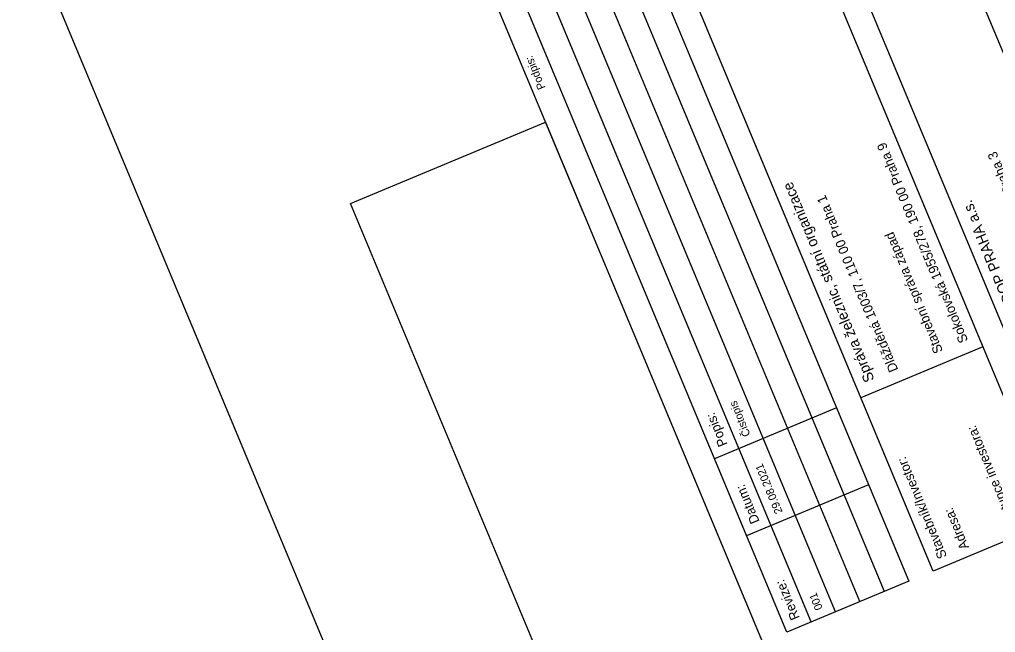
# Model space of a CAD drawing. Extents: x -834064 to -833847, y -1109181 to -1108930.
# Drawn here: x -834064.4 to -833967.4, y -1109058.9 to -1108998 of the extents above; entities that cross this region are included whole.
import ezdxf

# ---------------------------------------------------------------- set-up
doc = ezdxf.new("R2010")
doc.units = 0
for name, color, linetype in [('Rozpiska_pola_3', 7, 'Continuous'), ('Rozpiska_pole_4', 7, 'Continuous'), ('Rozpiska_pole_5', 7, 'Continuous'), ('Rozpiska_pole_6', 7, 'Continuous'), ('Rozpiska_pole_7', 7, 'Continuous'), ('Rozpiska_SŽ_netisknutelná', 7, 'Continuous'), ('Vrstva 63', 7, 'Continuous')]:
    doc.layers.add(name, color=color, linetype=linetype)

msp = doc.modelspace()

# ---------------------------------------------------------------- linework, layer by layer
at = {"layer": 'Rozpiska_pola_3'}
msp.add_line((-834008.401, -1109017.203), (-834024.933, -1108977.534), dxfattribs=at)
at = {"layer": 'Rozpiska_pole_4'}
for p, q in [((-833978.485, -1109054.868), (-834012.818, -1108972.485)), ((-833980.908, -1109055.877), (-834015.241, -1108973.495)), ((-833983.331, -1109056.887), (-834017.664, -1108974.505)), ((-833985.754, -1109057.897), (-834020.087, -1108975.514)), ((-833983.242, -1109036.63), (-833995.357, -1109041.679)), ((-833980.051, -1109044.287), (-833992.166, -1109049.336))]:
    msp.add_line(p, q, dxfattribs=at)
msp.add_lwpolyline([(-833988.177, -1109058.907), (-834022.51, -1108976.524), (-834010.395, -1108971.475), (-833976.062, -1109053.858)], close=True, dxfattribs=at)
at = {"layer": 'Rozpiska_pole_5'}
msp.add_line((-833968.704, -1109030.572), (-833980.819, -1109035.62), dxfattribs=at)
msp.add_lwpolyline([(-833973.639, -1109052.848), (-834007.972, -1108970.466), (-833995.857, -1108965.417), (-833961.524, -1109047.799)], close=True, dxfattribs=at)
at = {"layer": 'Rozpiska_pole_6'}
msp.add_lwpolyline([(-833959.101, -1109046.789), (-833993.434, -1108964.407), (-833969.203, -1108954.309), (-833934.871, -1109036.692)], close=True, dxfattribs=at)
at = {"layer": 'Rozpiska_pole_7'}
msp.add_line((-833949.409, -1109042.75), (-833983.742, -1108960.368), dxfattribs=at)
at = {"layer": 'Rozpiska_SŽ_netisknutelná'}
msp.add_lwpolyline([(-834009.985, -1109067.995), (-834031.523, -1109016.312), (-834012.139, -1109008.234), (-833990.6, -1109059.916)], close=True, dxfattribs=at)
at = {"layer": 'Vrstva 63'}
msp.add_line((-833983.612, -1109181.188), (-834064.392, -1108987.352), dxfattribs=at)

# ---------------------------------------------------------------- texts
at = {"layer": 'Rozpiska_pola_3'}
msp.add_text('Podpis:', height=0.7875, rotation=112.62355, dxfattribs=at).set_placement((-834012.139, -1109004.821))
at = {"layer": 'Rozpiska_pole_4'}
for s, height, p in [('Čistopis', 0.7875, (-833991.77, -1109039.305)), ('Popis:', 0.945, (-833994.047, -1109040.254)), ('29.08.2021', 0.7875, (-833988.579, -1109046.961)), ('Datum:', 0.945, (-833990.857, -1109047.91)), ('Revize:', 0.945, (-833986.868, -1109057.481)), ('001', 0.7875, (-833984.59, -1109056.532))]:
    msp.add_text(s, height=height, rotation=112.62355, dxfattribs=at).set_placement(p)
at = {"layer": 'Rozpiska_pole_5'}
for s, height, p in [('Správa železnic, státní organizace', 1.05, (-833979.447, -1109033.827)), ('Zástupce investora:', 0.945, (-833965.216, -1109048.458)), ('Stavebník/Investor:', 0.945, (-833972.243, -1109051.386)), ('Adresa:', 0.945, (-833970.062, -1109050.478))]:
    msp.add_text(s, height=height, rotation=112.62355, dxfattribs=at).set_placement(p)
at = {"layer": 'Rozpiska_pole_6'}
for s, height, p in [('Sokolovská 1955/278, 190 00 Praha 9', 0.945, (-833970.146, -1109029.952)), ('Olšanská 1a, 130 80 Praha 3', 0.945, (-833961.1, -1109026.182)), ('Dlážděná 1003/7, 110 00 Praha 1', 0.945, (-833977.095, -1109032.847)), ('SUDOP PRAHA a.s.', 1.05, (-833964.909, -1109027.769)), ('Stavební správa západ', 0.945, (-833972.645, -1109030.993))]:
    msp.add_text(s, height=height, rotation=112.62355, dxfattribs=at).set_placement(p)

doc.saveas('drawing.dxf')
